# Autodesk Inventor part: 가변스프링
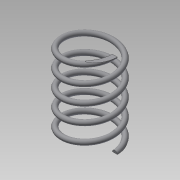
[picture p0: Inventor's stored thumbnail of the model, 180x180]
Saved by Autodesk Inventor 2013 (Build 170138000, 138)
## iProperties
Created: 2019-05
Part Number: 가변스프링
Material: 일반
Document SubType Name: Modeling
Designer: Administrator
Density: 1 g/cm^3
Mass: 0.973651 g
Surface Area: 19.7328 cm^2
Volume: 0.973651 cm^3
Author: Administrator
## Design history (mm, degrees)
sketch "스케치1"
  geometry: L1 (0, 0)-(10, 0); L2 (10, 0)-(10, 34); L3 (10, 34)-(0, 34); L4 (0, 34)-(0, 0); C1 r 1 at (10, 0)
  constraints: 8 end point, 2 parallel, 1 centre point, 1 coincident, 1 horizontal, 1 perpendicular
  dimensions: "d0" = 20 diameter of L2 L4; "d2" = 34 distance of L1.end L2.end (derived); "d3" = 2 diameter of C1
feature "코일1" sketch "스케치1" pitch "d4" = 10; turns "d6" = 5; dims "d5" = 34 (= d2), "d7" = 0, angle "d8" = 90 deg, angle "d9" = 90 deg, "d10" = 0, "d11" = 0
sketch "스케치2"
  geometry: L1 (34, 11.5)-(0, 11.5); L2 (0, 11.5)-(0, -11.5); L3 (0, -11.5)-(34, -11.5); L4 (34, -11.5)-(34, 11.5); 2 further points
  constraints: 8 end point, 2 parallel, 1 coincident, 1 horizontal, 1 midpoint, 1 perpendicular
  dimensions: "d12" = 23 distance of L1.end L2.end; "d14" = 34 distance of L2.end L3.end (derived)
extrude "돌출1" sketch "스케치2" stored distance "d15" = 23; taper "d16" = 0 deg
node "솔리드1"
